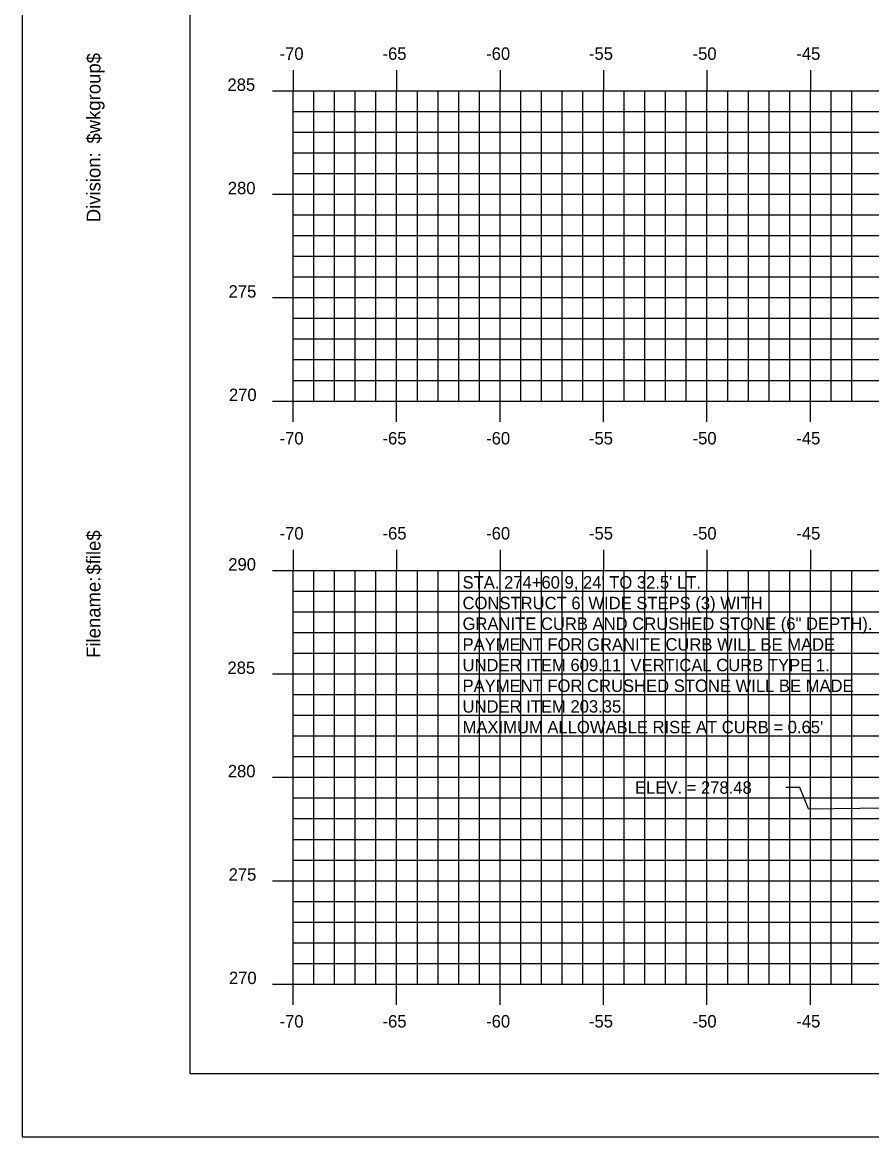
# Model space of a CAD drawing. Extents: x 853340 to 853510, y 366268 to 366378.
# Drawn here: x 853340 to 853381.1, y 366268.2 to 366322.1 of the extents above; entities that cross this region are included whole.
import ezdxf

# ---------------------------------------------------------------- set-up
doc = ezdxf.new("R2010")
doc.units = 0
for name, color, linetype in [('ANNOTATION', 7, 'Continuous'), ('BORDER', 7, 'Continuous'), ('D_Text_Standard', 7, 'Continuous'), ('H_V ANNOTATION', 7, 'Continuous'), ('MAJOR', 7, 'Continuous'), ('MINOR', 7, 'Continuous'), ('PLOT BOUNDARY', 7, 'Continuous'), ('S_Roadway_Centerline', 7, 'Continuous')]:
    doc.layers.add(name, color=color, linetype=linetype)

msp = doc.modelspace()

# ---------------------------------------------------------------- linework, layer by layer
at = {"layer": 'BORDER'}
for p, q in [((853348.1, 366376.236), (853348.1, 366271.236)), ((853348.1, 366271.236), (853508.1, 366271.236))]:
    msp.add_line(p, q, dxfattribs=at)
at = {"layer": 'D_Text_Standard'}
msp.add_lwpolyline([(853378.002, 366284.035), (853377.588, 366285.065), (853376.908, 366285.065)], dxfattribs=at)
at = {"layer": 'MAJOR'}
for p, q in [((853353.1, 366319.759), (853353.1, 366318.757)), ((853358.1, 366319.759), (853358.1, 366318.757)), ((853363.1, 366319.759), (853363.1, 366318.757)), ((853368.1, 366319.759), (853368.1, 366318.757)), ((853373.1, 366319.759), (853373.1, 366318.757)), ((853378.1, 366319.759), (853378.1, 366318.757)), ((853352.098, 366318.757), (853353.1, 366318.757)), ((853353.1, 366318.757), (853493.1, 366318.757)), ((853353.1, 366303.757), (853353.1, 366318.757)), ((853353.1, 366318.757), (853493.1, 366318.757)), ((853358.1, 366303.757), (853358.1, 366318.757)), ((853363.1, 366303.757), (853363.1, 366318.757)), ((853368.1, 366303.757), (853368.1, 366318.757)), ((853373.1, 366303.757), (853373.1, 366318.757)), ((853378.1, 366303.757), (853378.1, 366318.757)), ((853352.098, 366313.757), (853353.1, 366313.757)), ((853353.1, 366313.757), (853493.1, 366313.757)), ((853352.098, 366308.757), (853353.1, 366308.757)), ((853353.1, 366308.757), (853493.1, 366308.757)), ((853352.098, 366303.757), (853353.1, 366303.757)), ((853353.1, 366303.757), (853493.1, 366303.757)), ((853353.1, 366302.755), (853353.1, 366303.757)), ((853358.1, 366302.755), (853358.1, 366303.757)), ((853363.1, 366302.755), (853363.1, 366303.757)), ((853368.1, 366302.755), (853368.1, 366303.757)), ((853373.1, 366302.755), (853373.1, 366303.757)), ((853378.1, 366302.755), (853378.1, 366303.757)), ((853353.1, 366296.561), (853353.1, 366295.559)), ((853358.1, 366296.561), (853358.1, 366295.559)), ((853363.1, 366296.561), (853363.1, 366295.559)), ((853368.1, 366296.561), (853368.1, 366295.559)), ((853373.1, 366296.561), (853373.1, 366295.559)), ((853378.1, 366296.561), (853378.1, 366295.559)), ((853352.098, 366295.559), (853353.1, 366295.559)), ((853353.1, 366295.559), (853493.1, 366295.559)), ((853353.1, 366275.559), (853353.1, 366295.559)), ((853353.1, 366275.559), (853353.1, 366295.559)), ((853353.1, 366295.559), (853493.1, 366295.559)), ((853358.1, 366275.559), (853358.1, 366295.559)), ((853363.1, 366275.559), (853363.1, 366295.559)), ((853368.1, 366275.559), (853368.1, 366295.559)), ((853373.1, 366275.559), (853373.1, 366295.559)), ((853378.1, 366275.559), (853378.1, 366295.559)), ((853352.098, 366290.559), (853353.1, 366290.559)), ((853353.1, 366290.559), (853493.1, 366290.559)), ((853352.098, 366285.559), (853353.1, 366285.559)), ((853353.1, 366285.559), (853493.1, 366285.559)), ((853352.098, 366280.559), (853353.1, 366280.559)), ((853353.1, 366280.559), (853493.1, 366280.559)), ((853352.098, 366275.559), (853353.1, 366275.559)), ((853353.1, 366275.559), (853493.1, 366275.559)), ((853353.1, 366275.559), (853493.1, 366275.559)), ((853353.1, 366274.557), (853353.1, 366275.559)), ((853358.1, 366274.557), (853358.1, 366275.559)), ((853363.1, 366274.557), (853363.1, 366275.559)), ((853368.1, 366274.557), (853368.1, 366275.559)), ((853373.1, 366274.557), (853373.1, 366275.559)), ((853378.1, 366274.557), (853378.1, 366275.559))]:
    msp.add_line(p, q, dxfattribs=at)
at = {"layer": 'MINOR'}
for p, q in [((853354.1, 366303.757), (853354.1, 366318.757)), ((853355.1, 366303.757), (853355.1, 366318.757)), ((853356.1, 366303.757), (853356.1, 366318.757)), ((853357.1, 366303.757), (853357.1, 366318.757)), ((853359.1, 366303.757), (853359.1, 366318.757)), ((853360.1, 366303.757), (853360.1, 366318.757)), ((853361.1, 366303.757), (853361.1, 366318.757)), ((853362.1, 366303.757), (853362.1, 366318.757)), ((853364.1, 366303.757), (853364.1, 366318.757)), ((853365.1, 366303.757), (853365.1, 366318.757)), ((853366.1, 366303.757), (853366.1, 366318.757)), ((853367.1, 366303.757), (853367.1, 366318.757)), ((853369.1, 366303.757), (853369.1, 366318.757)), ((853370.1, 366303.757), (853370.1, 366318.757)), ((853371.1, 366303.757), (853371.1, 366318.757)), ((853372.1, 366303.757), (853372.1, 366318.757)), ((853374.1, 366303.757), (853374.1, 366318.757)), ((853375.1, 366303.757), (853375.1, 366318.757)), ((853376.1, 366303.757), (853376.1, 366318.757)), ((853377.1, 366303.757), (853377.1, 366318.757)), ((853379.1, 366303.757), (853379.1, 366318.757)), ((853380.1, 366303.757), (853380.1, 366318.757)), ((853353.1, 366317.757), (853493.1, 366317.757)), ((853353.1, 366317.757), (853354.102, 366317.757)), ((853353.1, 366316.757), (853493.1, 366316.757)), ((853353.1, 366316.757), (853354.102, 366316.757)), ((853353.1, 366315.757), (853493.1, 366315.757)), ((853353.1, 366315.757), (853354.102, 366315.757)), ((853353.1, 366314.757), (853493.1, 366314.757)), ((853353.1, 366314.757), (853354.102, 366314.757)), ((853353.1, 366312.757), (853493.1, 366312.757)), ((853353.1, 366312.757), (853354.102, 366312.757)), ((853353.1, 366311.757), (853493.1, 366311.757)), ((853353.1, 366311.757), (853354.102, 366311.757)), ((853353.1, 366310.757), (853493.1, 366310.757)), ((853353.1, 366310.757), (853354.102, 366310.757)), ((853353.1, 366309.757), (853493.1, 366309.757)), ((853353.1, 366309.757), (853354.102, 366309.757)), ((853353.1, 366307.757), (853493.1, 366307.757)), ((853353.1, 366307.757), (853354.102, 366307.757)), ((853353.1, 366306.757), (853493.1, 366306.757)), ((853353.1, 366306.757), (853354.102, 366306.757)), ((853353.1, 366305.757), (853493.1, 366305.757)), ((853353.1, 366305.757), (853354.102, 366305.757)), ((853353.1, 366304.757), (853493.1, 366304.757)), ((853353.1, 366304.757), (853354.102, 366304.757)), ((853354.1, 366275.559), (853354.1, 366295.559)), ((853355.1, 366275.559), (853355.1, 366295.559)), ((853356.1, 366275.559), (853356.1, 366295.559)), ((853357.1, 366275.559), (853357.1, 366295.559)), ((853359.1, 366275.559), (853359.1, 366295.559)), ((853360.1, 366275.559), (853360.1, 366295.559)), ((853361.1, 366275.559), (853361.1, 366295.559)), ((853362.1, 366275.559), (853362.1, 366295.559)), ((853364.1, 366275.559), (853364.1, 366295.559)), ((853365.1, 366275.559), (853365.1, 366295.559)), ((853366.1, 366275.559), (853366.1, 366295.559)), ((853367.1, 366275.559), (853367.1, 366295.559)), ((853369.1, 366275.559), (853369.1, 366295.559)), ((853370.1, 366275.559), (853370.1, 366295.559)), ((853371.1, 366275.559), (853371.1, 366295.559)), ((853372.1, 366275.559), (853372.1, 366295.559)), ((853374.1, 366275.559), (853374.1, 366295.559)), ((853375.1, 366275.559), (853375.1, 366295.559)), ((853376.1, 366275.559), (853376.1, 366295.559)), ((853377.1, 366275.559), (853377.1, 366295.559)), ((853379.1, 366275.559), (853379.1, 366295.559)), ((853380.1, 366275.559), (853380.1, 366295.559)), ((853353.1, 366294.559), (853493.1, 366294.559)), ((853353.1, 366294.559), (853354.102, 366294.559)), ((853353.1, 366293.559), (853493.1, 366293.559)), ((853353.1, 366293.559), (853354.102, 366293.559)), ((853353.1, 366292.559), (853493.1, 366292.559)), ((853353.1, 366292.559), (853354.102, 366292.559)), ((853353.1, 366291.559), (853493.1, 366291.559)), ((853353.1, 366291.559), (853354.102, 366291.559)), ((853353.1, 366289.559), (853493.1, 366289.559)), ((853353.1, 366289.559), (853354.102, 366289.559)), ((853353.1, 366288.559), (853493.1, 366288.559)), ((853353.1, 366288.559), (853354.102, 366288.559)), ((853353.1, 366287.559), (853493.1, 366287.559)), ((853353.1, 366287.559), (853354.102, 366287.559)), ((853353.1, 366286.559), (853493.1, 366286.559)), ((853353.1, 366286.559), (853354.102, 366286.559)), ((853353.1, 366284.559), (853493.1, 366284.559)), ((853353.1, 366284.559), (853354.102, 366284.559)), ((853353.1, 366283.559), (853493.1, 366283.559)), ((853353.1, 366283.559), (853354.102, 366283.559)), ((853353.1, 366282.559), (853493.1, 366282.559)), ((853353.1, 366282.559), (853354.102, 366282.559)), ((853353.1, 366281.559), (853493.1, 366281.559)), ((853353.1, 366281.559), (853354.102, 366281.559)), ((853353.1, 366279.559), (853493.1, 366279.559)), ((853353.1, 366279.559), (853354.102, 366279.559)), ((853353.1, 366278.559), (853493.1, 366278.559)), ((853353.1, 366278.559), (853354.102, 366278.559)), ((853353.1, 366277.559), (853493.1, 366277.559)), ((853353.1, 366277.559), (853354.102, 366277.559)), ((853353.1, 366276.559), (853493.1, 366276.559)), ((853353.1, 366276.559), (853354.102, 366276.559))]:
    msp.add_line(p, q, dxfattribs=at)
at = {"layer": 'PLOT BOUNDARY'}
msp.add_lwpolyline([(853340.007, 366268.177), (853510.007, 366268.177), (853510.007, 366378.177), (853340.007, 366378.177)], close=True, dxfattribs=at)
at = {"layer": 'S_Roadway_Centerline'}
msp.add_lwpolyline([(853378.002, 366284.035), (853391.663, 366284.218), (853393.728, 366284.501), (853401.276, 366285.894), (853404.575, 366286.053), (853410.582, 366286.432), (853411.503, 366286.496), (853422.159, 366286.693), (853423.104, 366286.714), (853424.096, 366286.691), (853435.982, 366286.375), (853440.609, 366286.208), (853442.522, 366286.163), (853448.883, 366285.971), (853449.042, 366286.069), (853449.557, 366286.324), (853451.29, 366286.654), (853460.175, 366287.602), (853462.142, 366287.892)], dxfattribs=at)

# ---------------------------------------------------------------- texts
at = {"layer": 'ANNOTATION'}
for s, p in [("STA. 274+60.9, 24' TO 32.5' LT.", (853361.285, 366294.688)), ("CONSTRUCT 6' WIDE STEPS (3) WITH", (853361.285, 366293.688)), ('GRANITE CURB AND CRUSHED STONE (6" DEPTH).', (853361.285, 366292.688)), ('PAYMENT FOR GRANITE CURB WILL BE MADE', (853361.285, 366291.688)), ('UNDER ITEM 609.11_VERTICAL CURB TYPE 1.', (853361.285, 366290.688)), ('PAYMENT FOR CRUSHED STONE WILL BE MADE', (853361.285, 366289.688)), ('UNDER ITEM 203.35.', (853361.285, 366288.688)), ("MAXIMUM ALLOWABLE RISE AT CURB = 0.65'", (853361.285, 366287.688))]:
    msp.add_text(s, height=0.6, dxfattribs=at).set_placement(p)
at = {"layer": 'BORDER'}
for s, p in [('$wkgroup$', (853343.785, 366316.206)), ('Division:', (853343.785, 366312.403)), ('$file$', (853343.785, 366295.362)), ('Filename:', (853343.785, 366291.335))]:
    msp.add_text(s, height=0.6696, rotation=90, dxfattribs=at).set_placement(p)
at = {"layer": 'D_Text_Standard'}
msp.add_text('ELEV. = 278.48', height=0.6, dxfattribs=at).set_placement((853369.62, 366284.765))
at = {"layer": 'H_V ANNOTATION'}
for s, p in [('-70', (853352.441, 366320.257)), ('-65', (853357.417, 366320.257)), ('-60', (853362.425, 366320.257)), ('-55', (853367.396, 366320.257)), ('-50', (853372.404, 366320.257)), ('-45', (853377.417, 366320.257)), ('285', (853349.924, 366318.757)), ('280', (853349.94, 366313.757)), ('275', (853349.978, 366308.757)), ('270', (853349.994, 366303.757)), ('-70', (853352.441, 366301.657)), ('-65', (853357.417, 366301.657)), ('-60', (853362.425, 366301.657)), ('-55', (853367.396, 366301.657)), ('-50', (853372.404, 366301.657)), ('-45', (853377.417, 366301.657)), ('-70', (853352.441, 366297.059)), ('-65', (853357.417, 366297.059)), ('-60', (853362.425, 366297.059)), ('-55', (853367.396, 366297.059)), ('-50', (853372.404, 366297.059)), ('-45', (853377.417, 366297.059)), ('290', (853349.962, 366295.559)), ('285', (853349.924, 366290.559)), ('280', (853349.94, 366285.559)), ('275', (853349.978, 366280.559)), ('270', (853349.994, 366275.559)), ('-70', (853352.441, 366273.459)), ('-65', (853357.417, 366273.459)), ('-60', (853362.425, 366273.459)), ('-55', (853367.396, 366273.459)), ('-50', (853372.404, 366273.459)), ('-45', (853377.417, 366273.459))]:
    msp.add_text(s, height=0.6, dxfattribs=at).set_placement(p)
at = {"layer": 'MAJOR'}
msp.add_text('-', height=0.00000006, rotation=53.1301, dxfattribs=at).set_placement((853353.095, 366275.559))

doc.saveas('drawing.dxf')
